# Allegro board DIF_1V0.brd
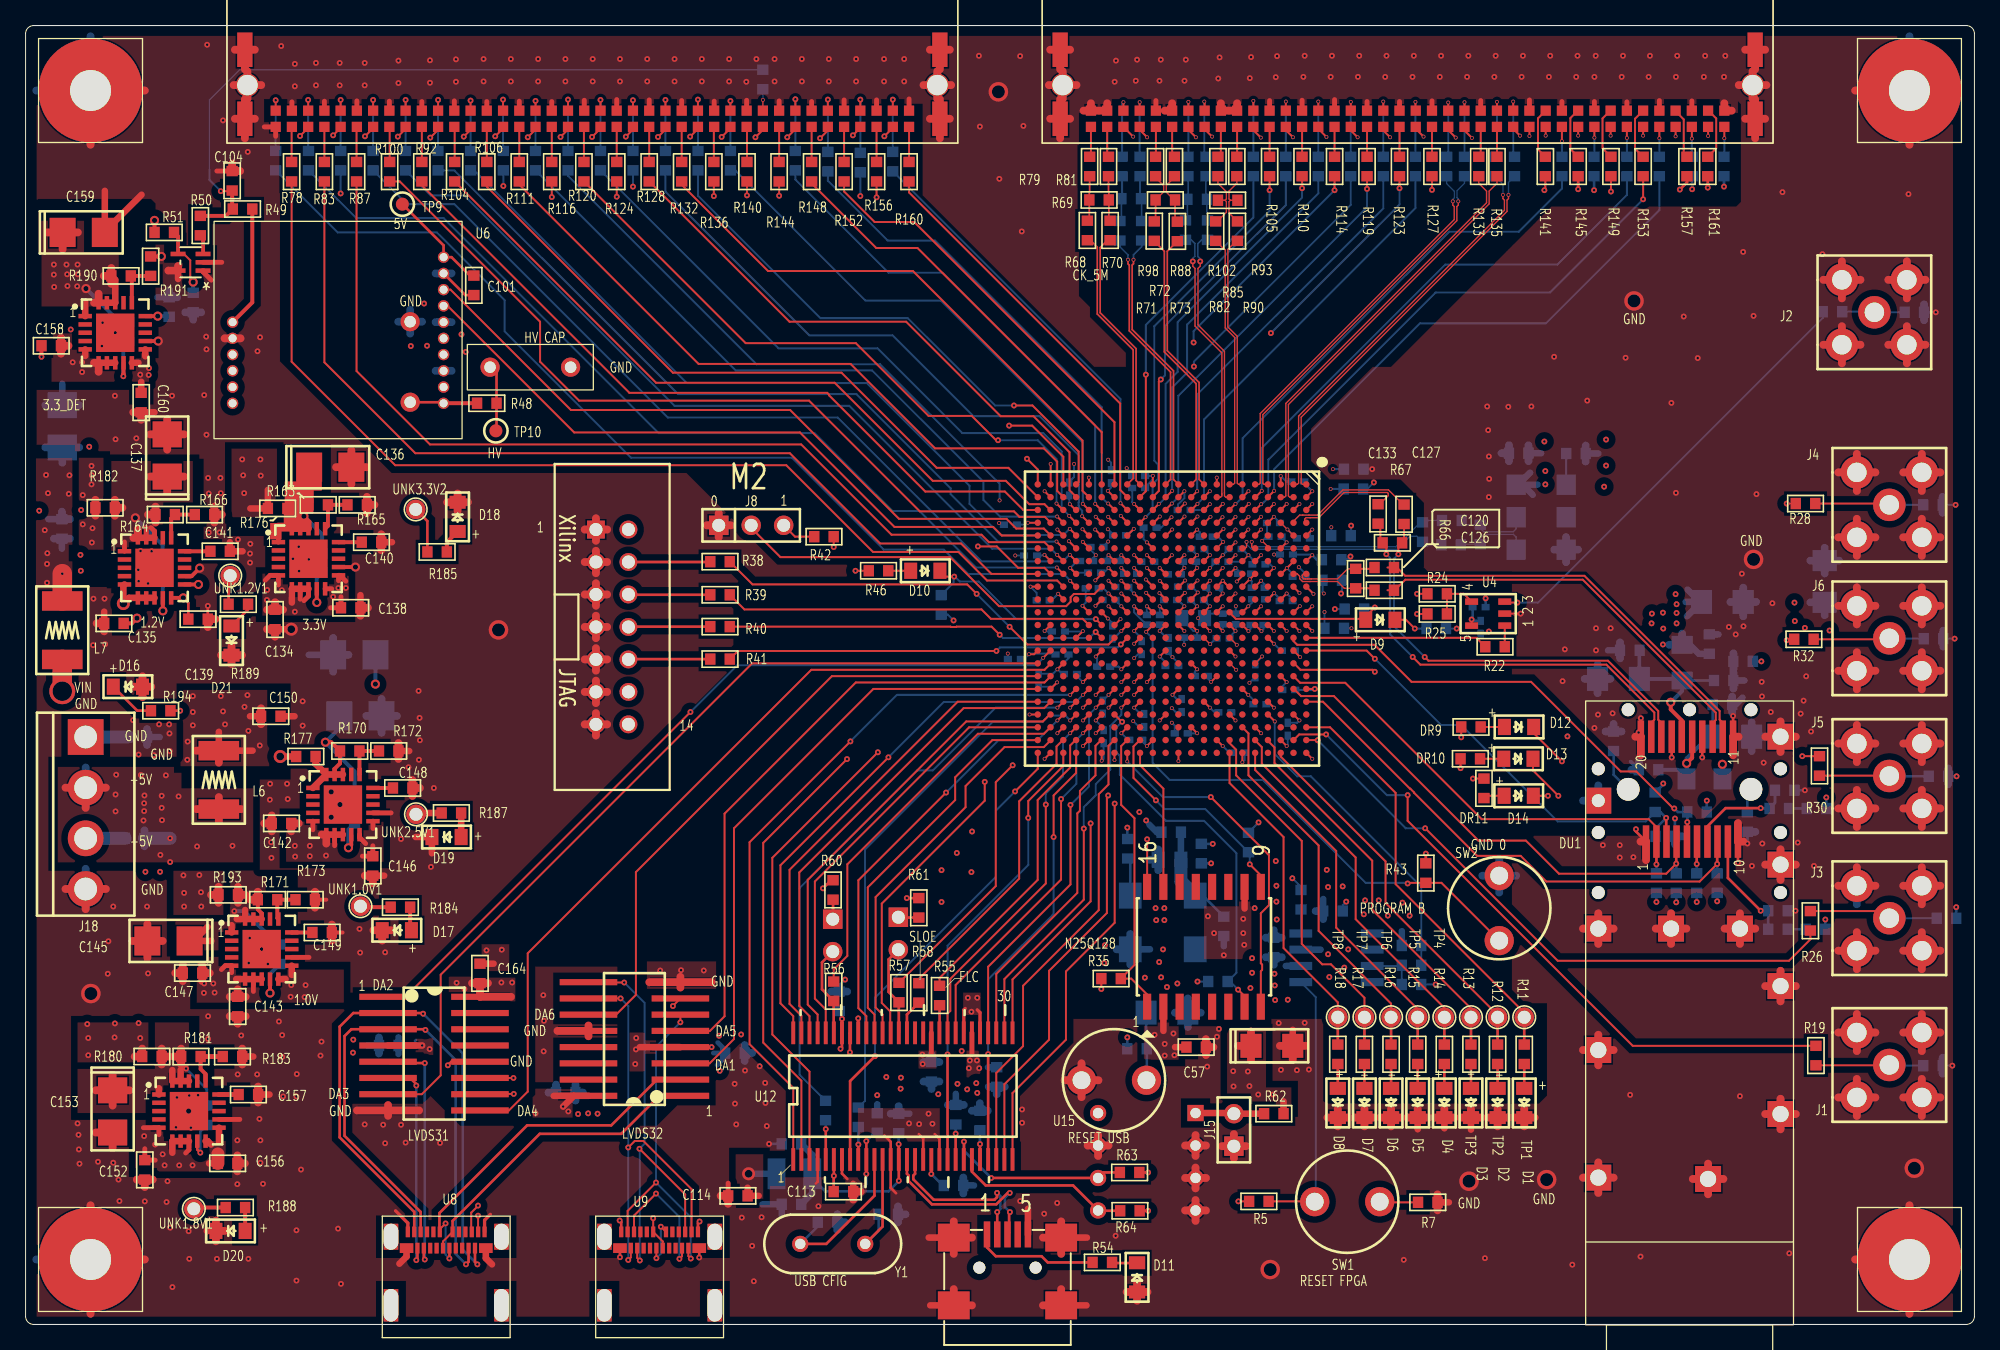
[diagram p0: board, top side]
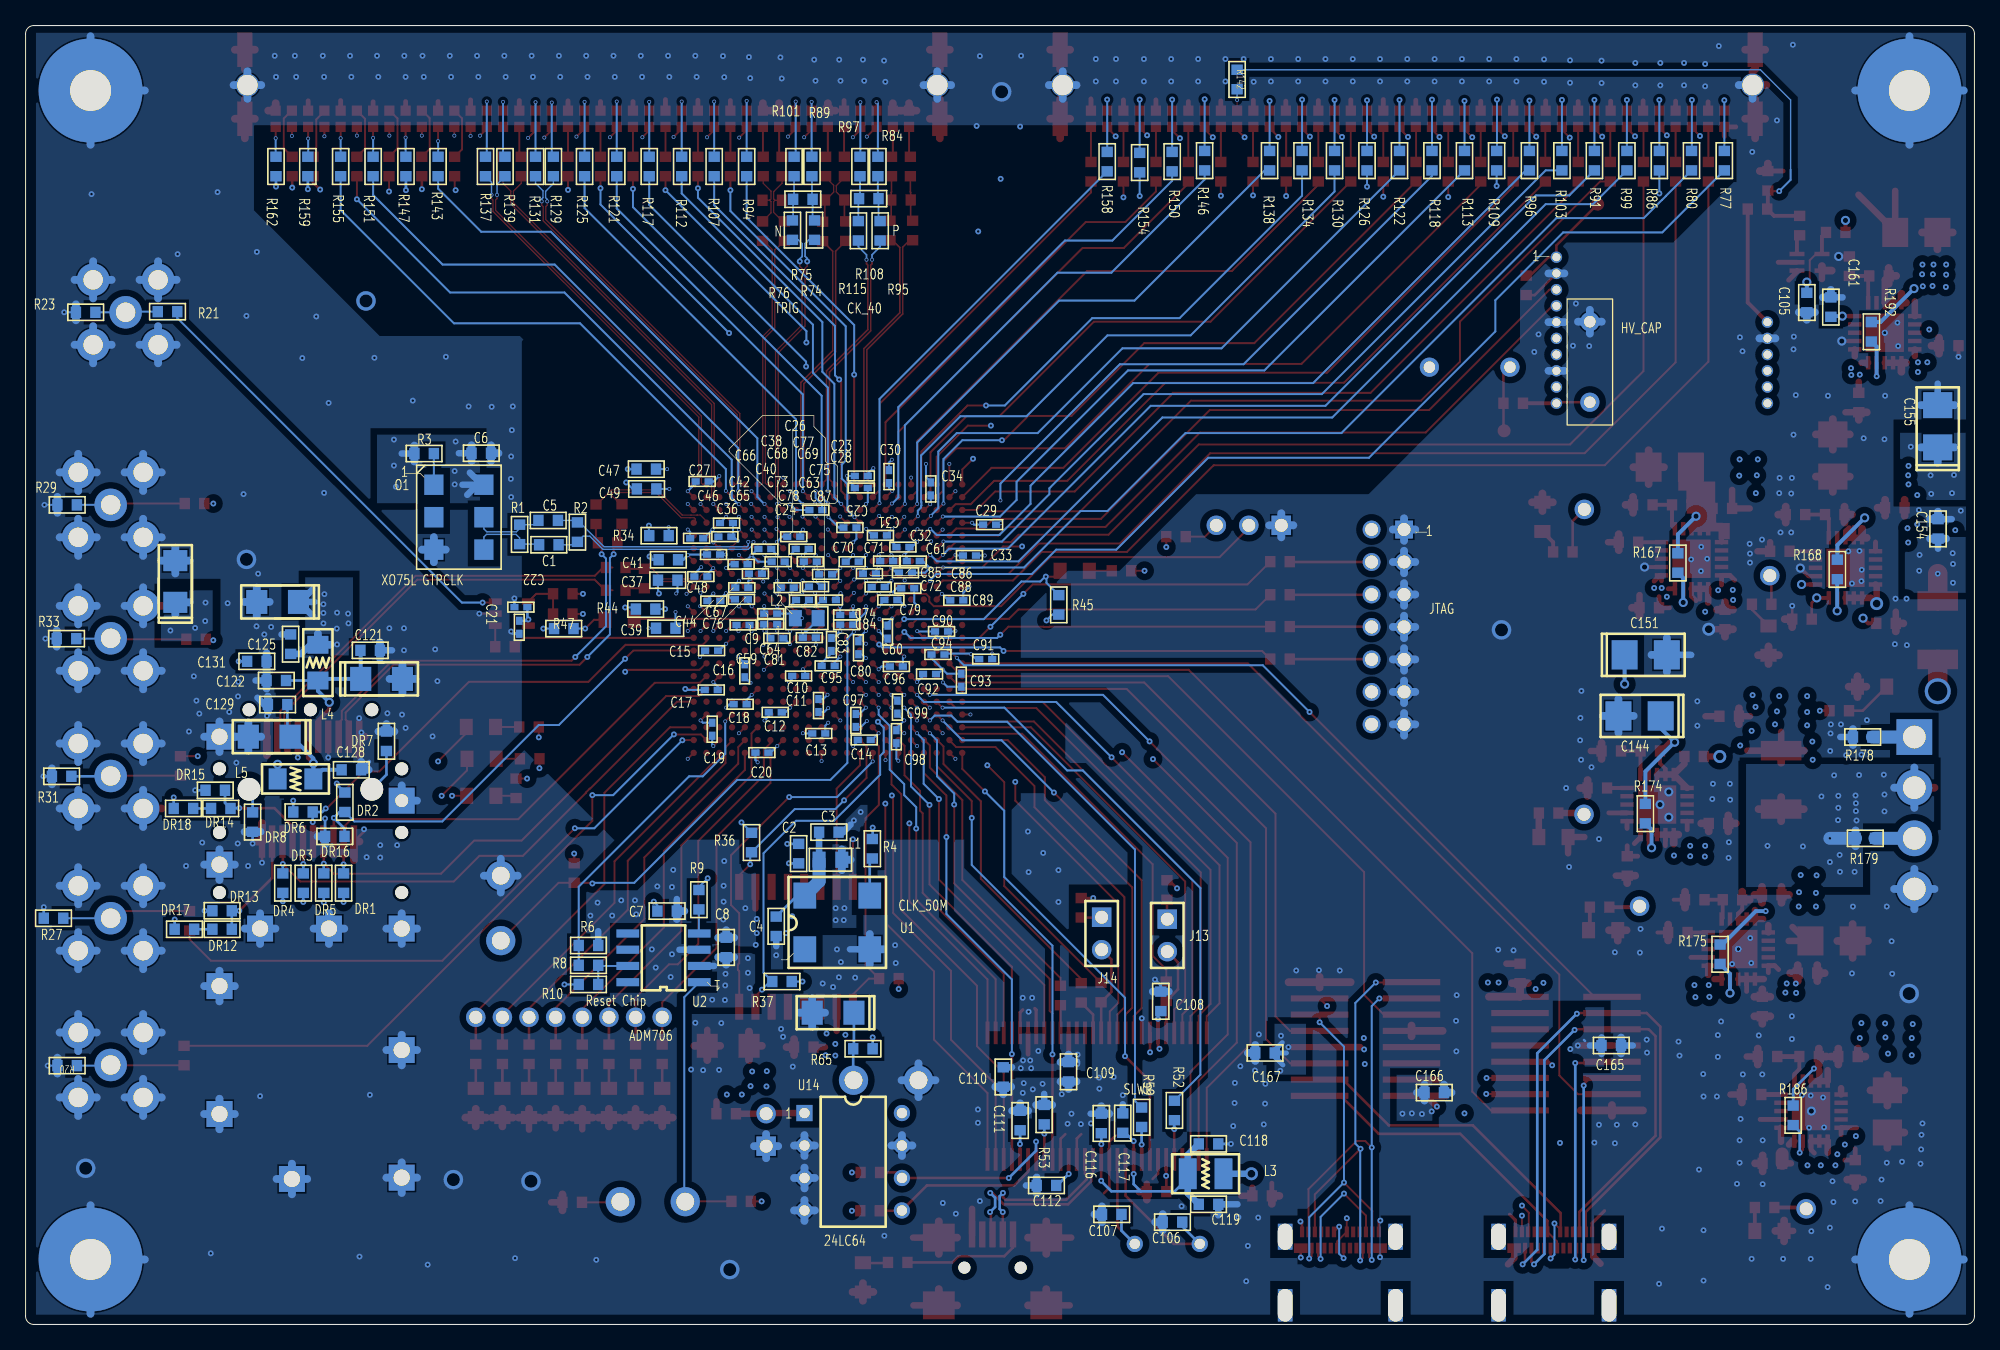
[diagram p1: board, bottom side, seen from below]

Outline 152.4 x 101.6 mm; copper layers: TOP, ART2, PLANE3, GND4, PLANE5, GND6, PLANE7, BOTTOM. Coordinates in mm from the lower left corner of the outline.
Outline path: 0,100.97 0,0.64 arc(0.19,0.19) 0.64,0 151.76,0 arc(152.21,0.19) 152.4,0.64 152.4,100.97 arc(152.21,101.41) 151.76,101.6 0.64,101.6 arc(0.19,101.41) 0,100.97

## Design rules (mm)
net group 5.0V_HV: nets N16783629 N16783633
net group CK_40M_F: nets N31992 N31996
net group CLK_5M_F: nets N31695 N31699
net group GTP1: nets N16065 N16069
net group GTP2: nets N16073 N16077
net group GTP_REFCLK: nets N63573 N65349
net group IN_MONITOR: nets IN_MONITOR N16789996
net group IO_PRE_2.5_1: nets IO_PRE_2.5_1 N16790016
net group IO_PRE_2.5_2: nets IO_PRE_2.5_2 N16840818
net group IO_PRE_2.5_3: nets IO_PRE_2.5_3 N16841427
net group IO_PRE_2.5_4: nets IO_PRE_2.5_4 N16790120
net group IO_PRE_2.5_5: nets IO_PRE_2.5_5 N16790006
net group IO_PRE_2.5_6: nets IO_PRE_2.5_6 N16841941
net group IO_PRE_2.5_7: nets IO_PRE_2.5_7 N16790130
net group IO_PRE_2.5_8: nets IO_PRE_2.5_8 N16790031
net group IO_PRE_2.5_9: nets IO_PRE_2.5_9 N16790140
net group IO_PRE_2.5_10: nets IO_PRE_2.5_10 N16790036
net group IO_PRE_2.5_11: nets IO_PRE_2.5_11 N16790145
net group IO_PRE_3.3_1: nets IO_PRE_3.3_1 N16783654
net group IO_PRE_3.3_2: nets IO_PRE_3.3_2 N1678375638
net group IO_PRE_3.3_3: nets IO_PRE_3.3_3 N16783650
net group IO_PRE_3.3_4: nets IO_PRE_3.3_4 N1678375636
net group IO_PRE_3.3_5: nets IO_PRE_3.3_5 N16783646
net group IO_PRE_3.3_6: nets IO_PRE_3.3_6 N1678375634
net group IO_PRE_3.3_7: nets IO_PRE_3.3_7 N16783642
net group IO_PRE_3.3_8: nets IO_PRE_3.3_8 N1678375632
net group IO_PRE_3.3_9: nets IO_PRE_3.3_9 N16783637
net group IO_PRE_3.3_10: nets IO_PRE_3.3_10 N1678375628
net group IO_PRE_3.3_11: nets IO_PRE_3.3_11 N16783603
net group IO_PRE_3.3_12: nets IO_PRE_3.3_12 N1678375618
net group IO_PRE_3.3_13: nets IO_PRE_3.3_13 N1678375624
net group IO_PRE_3.3_14: nets IO_PRE_3.3_14 N16783624
net group IO_PRE_3.3_15: nets IO_PRE_3.3_15 N1678375626
net group N65373: nets N65373 N607665
net group N606320: nets N65361 N606320
net group N16783572: nets N39711 N16783572
net group N16783577: nets N39253 N16783577
net group N16783581: nets N38992 N16783581
net group N16783585: nets N34554 N16783585
net group N16783590: nets N38404 N16783590
net group N16783594: nets N38396 N16783594
net group N16783598: nets N36779 N16783598
net group N16783607: nets N40733 N16783607
net group N16783611: nets N42476 N16783611
net group N16783616: nets N42251 N16783616
net group N16783620: nets N41303 N16783620
net group N16789976: nets N33890 N16789976
net group N16789981: nets N28287 N16789981
net group N16789986: nets N27930 N16789986
net group N16789991: nets N27061 N16789991
net group N16790001: nets N29237 N16790001
net group N16790021: nets N72632 N16790021
net group N16790026: nets N16790026 N16790135
net group N16790085: nets N33886 N16790085
net group N16790090: nets N27703 N16790090
net group N16790095: nets N26834 N16790095
net group N16790100: nets N73220 N16790100
net group N16790105: nets N29233 N16790105
net group N16790110: nets N71766 N16790110
net group N167837560: nets N39940 N167837560
net group N167837562: nets N39482 N167837562
net group N167837564: nets N73812 N167837564
net group N167837566: nets N38635 N167837566
net group N167837568: nets N34550 N167837568
net group N1678375610: nets N38400 N1678375610
net group N1678375612: nets N36552 N1678375612
net group N1678375614: nets N37008 N1678375614
net group N1678375616: nets N40729 N1678375616
net group N1678375620: nets N42480 N1678375620
net group N1678375622: nets N42028 N1678375622
net group N1678375630: nets N64910 N1678375630
net group OUT_CK_5N_1: nets N16790060 OUT_CK_5N_1
net group OUT_CK_5P_1: nets N1679025740 OUT_CK_5P_1
net group OUT_CK_40N_1: nets N16838243 OUT_CK_40N_1
net group OUT_CK_40P_1: nets N16789956 OUT_CK_40P_1
net group OUT_RAZ_CHN_N_1: nets N16790080 OUT_RAZ_CHN_N_1
net group OUT_RAZ_CHN_P_1: nets N16839910 OUT_RAZ_CHN_P_1
net group OUT_TRIG_EXT_N_1: nets N16839386 OUT_TRIG_EXT_N_1
net group OUT_TRIG_EXT_P_1: nets N16789966 OUT_TRIG_EXT_P_1
net group OUT_VAL_EVT_N_1: nets N16790070 OUT_VAL_EVT_N_1
net group OUT_VAL_EVT_P_1: nets N16838862 OUT_VAL_EVT_P_1
net group RAZ_CHN_F: nets N33117 N33121
net group REFCLK: nets REFCLK+ REFCLK-
net group SFP_RD: nets GTP0_RD+ GTP0_RD-
net group SFP_TD: nets GTP0_TD+ GTP0_TD-
net group TRIG_EXP_F: nets N32289 N32293
net group USB_DATA: nets N16778188 N16778190
net group VAL_EVT_F: nets N31078 N31082
net group 1.2V: nets N17024
net group 3.3V_OUT_DET: nets N16790041 N16790052 N16790150 N16790155

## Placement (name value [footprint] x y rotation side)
C1  0.1u  [SC0603]  111.48 60.99 180 bottom
C2  0.1u  [SC0603]  91.95 36.83 270 bottom
C3  0.01u  [SC0603]  89.59 38.51 0 bottom
C4  1000p  [SC0603]  93.7 31.14 90 bottom
C5  0.1u  [SC0603]  111.53 62.89 180 bottom
C6  0.01u  [SC0603]  116.76 68.15 180 bottom
C7  0.01u  [SC0603]  102.23 32.33 180 bottom
C8  1u  [SC0603]  97.61 29.49 90 bottom
C9  1uf  [SC0402]  93.65 53.67 0 bottom
C10  0.01uf  [SC0402]  91.95 50.72 180 bottom
C11  1uf  [SC0402]  90.4 48.41 270 bottom
C12  0.01uf  [SC0402]  93.78 47.88 180 bottom
C13  1uf  [SC0402]  90.37 46.23 180 bottom
C14  0.01uf  [SC0402]  86.82 45.72 180 bottom
C15  1uf  [SC0402]  98.76 52.7 180 bottom
C16  0.01uf  [SC0402]  96.16 51.13 270 bottom
C17  1uf  [SC0402]  98.78 49.63 180 bottom
C18  0.01uf  [SC0402]  96.52 48.51 180 bottom
C19  1uf  [SC0402]  98.7 46.56 90 bottom
C20  0.01uf  [SC0402]  94.82 44.73 180 bottom
C21  0.1uF  [SC0402]  113.79 54.53 270 bottom
C22  0.01uf  [SC0402]  113.67 56.11 0 bottom
C23  1uf  [SC0402]  87.05 66.37 180 bottom
C24  0.01uf  [SC0402]  90.6 63.7 180 bottom
C25  1uf  [SC0402]  87.93 62.33 180 bottom
C26  0.01uf  [SC0402]  92.33 61.62 180 bottom
C27  1uf  [SC0402]  99.49 65.94 0 bottom
C28  0.01uf  [SC0402]  87.05 65.43 180 bottom
C29  1uf  [SC0402]  77.01 62.56 180 bottom
C30  0.01uf  [SC0402]  84.89 66.32 90 bottom
C31  1uf  [SC0402]  85.55 61.72 180 bottom
C32  0.01uf  [SC0402]  83.79 60.81 0 bottom
C33  1uf  [SC0402]  78.59 60.15 180 bottom
C34  0.01uf  [SC0402]  81.61 65.35 90 bottom
C36  0.1uF  [SC0402]  98.6 60.22 0 bottom
C37  4.7uf  [SC0603]  102.18 58.22 0 bottom
C38  0.1uF  [SC0402]  94.59 60.66 180 bottom
C39  4.7uf  [SC0603]  102.34 54.46 0 bottom
C40  0.1uF  [SC0402]  95.33 58.72 180 bottom
C41  4.7uf  [SC0603]  102.13 59.82 180 bottom
C42  0.1uF  [SC0402]  97.59 62.69 0 bottom
C44  0.1uF  [SC0402]  98.58 56.59 0 bottom
C46  0.1uF  [SC0402]  99.92 61.49 0 bottom
C47  4.7uf  [SC0603]  103.86 66.9 0 bottom
C48  0.1uF  [SC0402]  99.59 58.5 0 bottom
C49  4.7uf  [SC0603]  103.84 65.35 0 bottom
C57  0.1uF  [SC0603]  91.54 21.69 0 top
C58  10uF  [CT1206]  97.46 21.79 0 top
C59  1uf  [SC0402]  96.29 54.71 0 bottom
C60  0.01uf  [SC0402]  84.99 54.15 270 bottom
C61  1uf  [SC0402]  82.98 59.72 180 bottom
C63  1uf  [SC0402]  90.63 57.71 180 bottom
C64  0.01uf  [SC0402]  94.13 55.6 0 bottom
C65  1uf  [SC0402]  97.71 61.62 0 bottom
C66  0.01uf  [SC0402]  96.44 59.46 0 bottom
C67  1uf  [SC0402]  96.39 57.63 0 bottom
C68  0.01uf  [SC0402]  93.55 59.66 180 bottom
C69  1uf  [SC0402]  91.03 59.66 180 bottom
C70  0.01uf  [SC0402]  87.76 59.66 180 bottom
C71  1uf  [SC0402]  85.06 59.72 180 bottom
C72  0.01uf  [SC0402]  85.72 57.68 180 bottom
C73  1uf  [SC0402]  92.84 57.63 180 bottom
C74  0.01uf  [SC0402]  88.19 55.5 0 bottom
C75  1uf  [SC0402]  89.84 58.67 0 bottom
C76  0.01uf  [SC0402]  96.42 56.72 180 bottom
C77  1uf  [SC0402]  91.67 60.66 180 bottom
C78  0.01uf  [SC0402]  91.64 56.67 180 bottom
C79  1uf  [SC0402]  84.73 56.67 180 bottom
C80  0.01uf  [SC0402]  87.27 52.93 270 bottom
C81  1uf  [SC0402]  94.13 54.76 0 bottom
C82  0.01uf  [SC0402]  91.11 53.72 180 bottom
C83  1uf  [SC0402]  89.38 53.19 270 bottom
C84  0.01uf  [SC0402]  88.19 54.74 180 bottom
C85  1uf  [SC0402]  86.41 58.72 180 bottom
C86  0.01uf  [SC0402]  83.59 58.8 180 bottom
C87  1uf  [SC0402]  89.53 56.67 180 bottom
C88  0.01uf  [SC0402]  83.41 57.58 180 bottom
C89  1uf  [SC0402]  79.58 56.64 180 bottom
C90  0.01uf  [SC0402]  80.77 54.2 180 bottom
C91  1uf  [SC0402]  77.32 52.04 180 bottom
C92  0.01uf  [SC0402]  81.71 50.88 180 bottom
C93  1uf  [SC0402]  79.22 50.39 90 bottom
C94  0.01uf  [SC0402]  81.05 52.4 0 bottom
C95  1uf  [SC0402]  89.64 51.51 0 bottom
C96  0.01uf  [SC0402]  84.3 51.46 180 bottom
C97  1uf  [SC0402]  87.48 47.24 270 bottom
C98  0.01uf  [SC0402]  84.3 45.97 270 bottom
C99  1uf  [SC0402]  84.23 48.29 90 bottom
C101  0.1u  [SC0603]  35.05 81.28 90 top
C102  47n  [CHV]  30.07 72.14 90 bottom
C103  47n  [CHV]  36.32 74.88 0 top
C104  0.1u  [SC0603]  16.15 89.46 90 top
C105  0.1u  [SC0603]  13.11 79.93 270 bottom
C106  12pF  [SC0603]  62.71 8 180 bottom
C107  12pF  [SC0603]  67.46 8.61 180 bottom
C108  0.1uF  [SC0603]  63.63 25.27 270 bottom
C109  0.1uF  [SC0603]  70.84 19.76 90 bottom
C110  0.1uF  [SC0603]  75.95 19.35 90 bottom
C111  0.1uF  [SC0603]  74.63 15.95 270 bottom
C112  0.1uF  [SC0603]  72.57 10.87 180 bottom
C113  0.1uF  [SC0603]  63.96 10.39 180 top
C114  0.1uF  [SC0603]  55.7 10.06 0 top
C115  10uF  [CT1206]  89.26 24.38 0 bottom
C116  0.1uF  [SC0603]  68.28 15.72 270 bottom
C117  0.1uF  [SC0603]  66.6 15.75 270 bottom
C118  10uF  [SC0603]  59.89 14.12 0 bottom
C119  0.1uF  [SC0603]  59.89 9.4 0 bottom
C120  0.1uF  [SC0603]  106.25 59.21 180 top
C121  1uF  [SC0603]  125.45 52.73 180 bottom
C122  0.1uF  [SC0603]  132.79 50.37 0 bottom
C123  10uF  [CT1206]  124.56 50.5 180 bottom
C124  10uF  [CT1206]  140.69 58.12 90 bottom
C125  0.1uF  [SC0603]  131.67 53.21 90 bottom
C126  0.1uF  [SC0603]  106.25 57.43 180 top
C127  0.1uF  [SC0603]  107.8 63.37 270 top
C128  1uF  [SC0603]  126.92 43.38 180 bottom
C129  0.1uF  [SC0603]  132.69 48.49 0 bottom
C130  10uF  [CT1206]  133.35 45.97 0 bottom
C131  0.1uF  [SC0603]  134.32 51.87 180 bottom
C132  10uF  [CT1206]  132.69 56.52 0 bottom
C133  0.1uF  [SC0603]  105.77 63.4 270 top
C134  1u  [SC0603]  19.51 55.14 270 top
C135  1u  [SC0603]  6.91 54.84 180 top
C136  10u  [STC3528]  23.83 67.06 0 top
C137  10u  [STC3528]  11.07 67.97 90 top
C138  1u  [SC0603]  25.43 56.06 0 top
C139  1u  [SC0603]  13.49 55.17 0 top
C140  470p  [SC0603]  27.05 61.19 0 top
C141  470p  [SC0603]  15.21 60.48 0 top
C142  1u  [SC0603]  20.02 39.19 180 top
C143  1u  [SC0603]  16.59 24.87 270 top
C144  10u  [STC3528]  26.19 47.6 0 bottom
C145  10u  [STC3528]  11.18 30 180 top
C146  1u  [SC0603]  27.15 35.86 270 top
C147  1u  [SC0603]  13.06 27.48 180 top
C148  470p  [SC0603]  29.49 41.96 0 top
C149  470p  [SC0603]  23.19 30.66 0 top
C150  0.1u  [SC0603]  19.18 47.57 0 top
C151  10u  [STC3528]  25.7 52.37 180 bottom
C152  1u  [SC0603]  9.32 12.09 270 top
C153  10u  [STC3528]  6.81 16.66 270 top
C154  0.1u  [SC0603]  2.84 62.23 90 bottom
C155  10u  [STC3528]  2.87 70.26 90 bottom
C156  1u  [SC0603]  15.8 12.6 0 top
C157  470p  [SC0603]  17.42 17.98 0 top
C158  1u  [SC0603]  2.01 76.56 180 top
C159  10u  [STC3528]  4.55 85.42 0 top
C160  1u  [SC0603]  9.04 72.11 270 top
C161  470p  [SC0603]  11.23 79.58 90 bottom
C164  0.1uF  [SC0603]  35.53 27.46 270 top
C165  0.1uF  [SC0603]  28.4 21.82 0 bottom
C166  0.1uF  [SC0603]  42.24 18.14 0 bottom
C167  0.1uF  [SC0603]  55.47 21.23 180 bottom
D1  LED  [SD0805]  117.2 17.32 90 top
D2  LED  [SD0805]  115.11 17.32 90 top
D3  LED  [SD0805]  113.03 17.32 90 top
D4  LED  [SD0805]  110.95 17.32 90 top
D5  LED  [SD0805]  108.86 17.32 90 top
D6  LED  [SD0805]  106.78 17.32 90 top
D7  LED  [SD0805]  104.7 17.32 90 top
D8  LED  [SD0805]  102.62 17.32 90 top
D9  LED  [SD0805]  105.94 55.12 180 top
D10  LED  [SD0805]  70.36 58.95 180 top
D11  LED  [SD0805]  86.92 3.68 270 top
D12  LED  [SD0805]  116.79 46.74 180 top
D13  LED  [SD0805]  116.74 44.25 180 top
D14  LED  [SD0805]  116.76 41.35 180 top
D16  Green  [SD0805]  8 49.89 0 top
D17  LED  [SD0805]  29.03 30.84 0 top
D18  LED  [SD0805]  33.78 63.17 270 top
D19  LED  [SD0805]  32.92 38.13 0 top
D20  LED  [SD0805]  16.03 7.32 0 top
D21  LED  [SD0805]  16.1 53.49 90 top
DR1  4.7K  [SR0603]  127.53 34.52 270 bottom
DR2  4.7K  [SR0603]  127.43 40.84 90 bottom
DR3  4.7K  [SR0603]  130.68 34.52 270 bottom
DR4  4.7K  [SR0603]  132.28 34.52 270 bottom
DR5  4.7K  [SR0603]  129.08 34.52 270 bottom
DR6  4.7K  [SR0603]  130.71 40.08 0 bottom
DR7  null  [SR0603]  124.18 45.62 90 bottom
DR8  null  [SR0603]  134.65 39.29 270 bottom
DR9  4.7K  [SR0603]  113.03 46.74 180 top
DR10  4.7K  [SR0603]  112.98 44.25 180 top
DR11  4.7K  [SR0603]  114.05 41.94 90 top
DR12  4.7K  [SR0603]  137.03 30.91 0 bottom
DR13  4.7K  [SR0603]  137.03 32.36 0 bottom
DR14  4.7K  [SR0603]  137.13 40.36 0 bottom
DR15  4.7K  [SR0603]  137.57 41.78 0 bottom
DR16  4.7K  [SR0603]  128.22 38.18 0 bottom
DR17  4.7K  [SR0603]  139.98 30.91 180 bottom
DR18  4.7K  [SR0603]  140.06 40.36 180 bottom
DU1  74441-0010  [LASER22-4816-M]  126.72 37.77 90 top
J1  SMA  [CON-BNC-S-T]  145.75 20.29 0 top
J2  SMA  [CON-BNC-S-T]  144.58 79.17 0 top
J3  SMA  [CON-BNC-S-T]  145.75 31.78 0 top
J4  SMA  [CON-BNC-S-T]  145.75 64.11 0 top
J5  SMA  [CON-BNC-S-T]  145.75 42.9 0 top
J6  SMA  [CON-BNC-S-T]  145.75 53.67 0 top
J7  JTAG  [JTAG-14P]  41.38 67.31 270 top
J8  MSEL0  [SIP-3P]  56.74 62.51 0 top
J9  2mm_Hole  [2MM_HOLE]  147.32 96.52 0 top
J10  2mm_Hole  [2MM_HOLE]  147.32 5.08 0 top
J11  2mm_Hole  [2MM_HOLE]  5.08 96.52 0 top
J12  2mm_Hole  [2MM_HOLE]  5.08 5.08 0 top
J13  WU =1  [SIP-2P]  63.12 30.43 270 bottom
J14  WU2 =1  [SIP-2P]  68.25 30.58 270 bottom
J15  addrCS  [SIP-2P]  94.49 15.21 90 top
J16  CONN  [154744-ERNI]  19.56 94.95 90 top
J17  CONN  [154744-ERNI]  83.31 94.95 90 top
J18  Power In  [SIP-4P-156]  4.7 40.01 270 top
L1  BEAD  [SL0805]  89.46 36.35 0 bottom
L2  BEAD  [SL0805]  91.31 55.24 180 bottom
L3  Bead  [SL1210]  60.12 11.79 0 bottom
L4  39mH  [SL1206]  129.54 51.77 90 bottom
L5  39mH  [SL1206]  131.29 42.67 0 bottom
L6  10uH  [SL1812]  15.11 42.6 90 top
L7  10uH  [SL1812]  2.87 54.31 90 top
NOREF  -  []  114.33 87.96 0 top
NOREF#2  -  []  115.67 88.06 0 top
NOREF#3  -  []  0.64 101.6 0 top
NOREF#4  -  []  119.02 51.82 0 top
NOREF#5  -  []  83.85 81.08 0 top
NOREF#6  -  []  30.78 11.07 0 top
NOREF#7  -  []  91.54 81.51 0 top
NOREF#8  -  []  33.93 11.63 0 top
NOREF#9  -  []  5.08 96.52 0 top
NOREF#10  -  []  45.24 12.57 0 top
NOREF#11  -  []  89.26 82.5 0 top
NOREF#12  -  []  47.6 13.67 0 top
NOREF#13  -  []  117.42 58.39 0 top
NOREF#14  -  []  35.03 8.66 0 top
NOREF#15  -  []  49.63 10.72 0 top
NOREF#16  -  []  30.89 13.23 0 top
NOREF#17  -  []  32.69 22.1 0 top
NOREF#18  -  []  93.83 82.73 0 top
NOREF#19  -  []  0 0.64 90 top
NOREF#20  -  []  86.23 81.56 0 top
NOREF#21  -  []  5.08 5.08 90 top
NOREF#22  -  []  74.09 9.55 0 top
NOREF#23  -  []  24.87 21.59 0 top
NOREF#24  -  []  111.86 86.92 0 top
O1  100M  [XO75L]  118.52 63.14 270 bottom
R1  null  [SR0603]  113.77 61.8 90 bottom
R2  100  [SR0603]  109.25 61.98 90 bottom
R3  4.7K  [SR0603]  121.23 68.12 0 bottom
R4  33  [SR0603]  86.18 37.21 90 bottom
R5  10k  [SR0603]  96.44 9.63 180 top
R6  330  [SR0603]  108.38 29.64 0 bottom
R7  1k  [SR0603]  109.65 9.55 0 top
R8  100  [SR0603]  108.38 28.09 180 bottom
R9  100k  [SR0603]  99.75 33.22 90 bottom
R10  100k  [SR0603]  108.38 26.59 180 bottom
R11  1k  [SR0603]  117.2 21.13 270 top
R12  1k  [SR0603]  115.11 21.13 270 top
R13  1k  [SR0603]  113.03 21.13 270 top
R14  1k  [SR0603]  110.95 21.13 270 top
R15  1k  [SR0603]  108.86 21.13 270 top
R16  1k  [SR0603]  106.78 21.13 270 top
R17  1k  [SR0603]  104.7 21.13 270 top
R18  1k  [SR0603]  102.62 21.13 270 top
R19  test  [SR0603]  140 21.03 90 top
R20  test  [SR0603]  149.15 20.24 0 bottom
R21  0  [SR0603]  141.3 79.22 180 bottom
R22  33  [SR0603]  114.91 53.01 180 top
R23  50  [SR0603]  147.7 79.17 0 bottom
R24  3k  [SR0603]  110.39 57.15 180 top
R25  4k  [SR0603]  110.39 55.58 180 top
R26  test  [SR0603]  139.57 31.57 270 top
R27  test  [SR0603]  150.22 31.78 0 bottom
R28  test  [SR0603]  139.19 64.21 180 top
R29  test  [SR0603]  149.15 64.11 0 bottom
R30  test  [SR0603]  140.28 43.69 90 top
R31  test  [SR0603]  149.58 42.88 0 bottom
R32  test  [SR0603]  139.06 53.59 180 top
R33  test  [SR0603]  149.2 53.64 0 bottom
R34  100  [SR0603]  102.87 61.7 0 bottom
R35  4.7K  [SR0603]  84.89 27.05 180 top
R36  4.7K  [SR0603]  95.63 37.69 90 bottom
R37  4.7K  [SR0603]  93.24 26.82 180 bottom
R38  33  [SR0603]  54.31 59.66 0 top
R39  33  [SR0603]  54.31 57.07 0 top
R40  33  [SR0603]  54.31 54.58 0 top
R41  33  [SR0603]  54.31 52.04 0 top
R42  4.7K  [SR0603]  62.43 61.62 180 top
R43  4.7K  [SR0603]  109.5 35.31 90 top
R44  300  [SR0603]  103.91 55.96 180 bottom
R45  4.7K  [SR0603]  71.6 56.29 270 bottom
R46  300  [SR0603]  66.7 58.95 180 top
R47  220  [SR0603]  110.31 54.43 180 bottom
R48  10  [SR0603]  36.07 72.06 0 top
R49  1k  [SR0603]  16.97 87.25 0 top
R50  1.5k  [SR0603]  13.67 85.95 270 top
R51  10  [SR0603]  10.85 85.42 0 top
R52  0  [SR0603]  62.56 16.74 270 bottom
R53  10k  [SR0603]  72.75 16.41 270 bottom
R54  4.7k  [SR0603]  84.2 4.85 180 top
R55  0  [SR0603]  71.48 25.73 90 top
R56  0 or null  [SR0603]  63.2 26.06 270 top
R57  0 or null  [SR0603]  68.3 25.96 270 top
R58  0  [SR0603]  69.85 25.93 90 top
R59  0  [SR0603]  65.13 16.21 90 bottom
R60  0  [SR0603]  63.14 33.99 90 top
R61  0  [SR0603]  69.85 32.59 90 top
R62  10k  [SR0603]  97.61 16.48 0 top
R63  2.2k  [SR0603]  86.33 11.89 0 top
R64  2.2k  [SR0603]  86.36 8.89 0 top
R65  20k  [SR0603]  86.92 21.56 180 bottom
R66  100  [SR0603]  104.01 58.34 90 top
R67  100  [SR0603]  106.88 61.14 0 top
R68  0  [SR0603]  83.03 85.57 90 top
R69  100  [SR0603]  83.95 87.96 180 top
R70  0  [SR0603]  84.81 85.57 270 top
R71  0  [SR0603]  88.27 85.52 90 top
R72  100  [SR0603]  89.13 87.96 180 top
R73  0  [SR0603]  90.07 85.5 270 top
R74  0  [SR0603]  90.7 85.6 90 bottom
R75  100  [SR0603]  91.62 88.01 180 bottom
R76  0  [SR0603]  92.43 85.6 270 bottom
R77  0  [SR0603]  19.56 91.03 90 bottom
R78  0  [SR0603]  20.8 90.17 270 top
R79  0  [SR0603]  83.21 90.58 270 top
R80  0  [SR0603]  22.12 91.03 90 bottom
R81  0  [SR0603]  84.68 90.58 270 top
R82  0  [SR0603]  93.07 85.52 90 top
R83  0  [SR0603]  23.37 90.17 270 top
R84  0  [SR0603]  85.75 90.58 90 bottom
R85  100  [SR0603]  94.01 87.93 180 top
R86  0  [SR0603]  24.64 91.03 90 bottom
R87  0  [SR0603]  25.88 90.17 270 top
R88  0  [SR0603]  89.84 90.58 270 top
R89  0  [SR0603]  90.91 90.58 90 bottom
R90  0  [SR0603]  94.77 85.52 270 top
R91  0  [SR0603]  29.72 91.03 90 bottom
R92  0  [SR0603]  30.99 90.17 270 top
R93  0  [SR0603]  94.72 90.58 270 top
R94  0  [SR0603]  96.01 90.58 90 bottom
R95  0  [SR0603]  85.57 85.55 90 bottom
R96  0  [SR0603]  34.8 91.03 90 bottom
R97  0  [SR0603]  87.15 90.58 90 bottom
R98  0  [SR0603]  88.37 90.58 270 top
R99  0  [SR0603]  27.18 91.03 90 bottom
R100  0  [SR0603]  28.47 90.17 270 top
R101  0  [SR0603]  92.3 90.58 90 bottom
R102  0  [SR0603]  93.24 90.58 270 top
R103  0  [SR0603]  32.26 91.03 90 bottom
R104  0  [SR0603]  33.55 90.17 270 top
R105  0  [SR0603]  97.28 90.58 270 top
R106  0  [SR0603]  36.07 90.17 270 top
R107  0  [SR0603]  98.55 90.58 90 bottom
R108  100  [SR0603]  86.46 88.06 180 bottom
R109  0  [SR0603]  37.36 91.03 90 bottom
R110  0  [SR0603]  99.82 90.58 270 top
R111  0  [SR0603]  38.61 90.17 270 top
R112  0  [SR0603]  101.09 90.58 90 bottom
R113  0  [SR0603]  39.88 91.03 90 bottom
R114  0  [SR0603]  102.36 90.58 270 top
R115  0  [SR0603]  87.27 85.55 270 bottom
R116  0  [SR0603]  41.15 90.17 270 top
R117  0  [SR0603]  103.63 90.58 90 bottom
R118  0  [SR0603]  42.42 91.03 90 bottom
R119  0  [SR0603]  104.9 90.58 270 top
R120  0  [SR0603]  43.66 90.17 270 top
R121  0  [SR0603]  106.17 90.58 90 bottom
R122  0  [SR0603]  44.96 91.03 90 bottom
R123  0  [SR0603]  107.44 90.58 270 top
R124  0  [SR0603]  46.23 90.17 270 top
R125  0  [SR0603]  108.69 90.58 90 bottom
R126  0  [SR0603]  47.5 91.03 90 bottom
R127  0  [SR0603]  109.98 90.58 270 top
R128  0  [SR0603]  48.77 90.17 270 top
R129  0  [SR0603]  111.12 90.58 90 bottom
R130  0  [SR0603]  50.04 91.03 90 bottom
R131  0  [SR0603]  112.52 90.58 90 bottom
R132  0  [SR0603]  51.31 90.17 270 top
R133  0  [SR0603]  113.64 90.58 270 top
R134  0  [SR0603]  52.58 91.03 90 bottom
R135  0  [SR0603]  115.06 90.58 270 top
R136  0  [SR0603]  53.82 90.17 270 top
R137  0  [SR0603]  116.43 90.58 90 bottom
R138  0  [SR0603]  55.12 91.03 90 bottom
R139  0  [SR0603]  114.91 90.58 90 bottom
R140  0  [SR0603]  56.41 90.17 270 top
R141  0  [SR0603]  118.85 90.58 90 top
R142  0  [SR0603]  57.66 97.38 270 bottom
R143  0  [SR0603]  120.14 90.58 270 bottom
R144  0  [SR0603]  58.93 90.17 270 top
R145  0  [SR0603]  121.41 90.58 90 top
R146  0  [SR0603]  60.2 91.03 90 bottom
R147  0  [SR0603]  122.66 90.58 270 bottom
R148  0  [SR0603]  61.47 90.17 270 top
R149  0  [SR0603]  123.98 90.58 90 top
R150  0  [SR0603]  62.74 90.96 90 bottom
R151  0  [SR0603]  125.22 90.58 270 bottom
R152  0  [SR0603]  64.01 90.17 270 top
R153  0  [SR0603]  126.49 90.58 90 top
R154  0  [SR0603]  65.28 90.88 90 bottom
R155  0  [SR0603]  127.76 90.58 270 bottom
R156  0  [SR0603]  66.55 90.17 270 top
R157  0  [SR0603]  129.92 90.58 90 top
R158  0  [SR0603]  67.82 90.96 90 bottom
R159  0  [SR0603]  130.33 90.58 270 bottom
R160  0  [SR0603]  69.09 90.17 270 top
R161  0  [SR0603]  131.55 90.58 90 top
R162  0  [SR0603]  132.82 90.58 270 bottom
R163  3.57k  [SR0603]  22.89 64.11 0 top
R164  2.49k  [SR0603]  10.92 63.35 0 top
R165  1.15k  [SR0603]  25.93 64.11 0 top
R166  4.99k  [SR0603]  14 63.35 0 top
R167  100k  [SR0603]  23.19 59.56 90 bottom
R168  100k  [SR0603]  10.72 59.05 90 bottom
R170  3.57k  [SR0603]  25.35 44.86 0 top
R171  1.13k  [SR0603]  18.92 33.22 0 top
R172  1.69k  [SR0603]  28.4 44.86 0 top
R173  4.53k  [SR0603]  21.87 33.22 0 top
R174  100k  [SR0603]  25.73 39.95 90 bottom
R175  100k  [SR0603]  19.89 28.96 90 bottom
R176  0  [SR0603]  19.71 63.83 180 top
R177  0  [SR0603]  21.92 44.42 180 top
R178  0  [SR0603]  8.74 45.95 0 bottom
R179  0  [SR0603]  8.53 38.02 0 bottom
R180  0  [SR0603]  9.88 20.95 180 top
R181  3.57k  [SR0603]  12.93 20.95 0 top
R182  0  [SR0603]  6.22 63.88 180 top
R183  2.87k  [SR0603]  16.18 20.95 0 top
R184  1.5k  [SR0603]  29.31 32.64 0 top
R185  1.5k  [SR0603]  32.18 60.43 0 top
R186  100k  [SR0603]  14.17 16.36 90 bottom
R187  1.5k  [SR0603]  33.3 40.01 0 top
R188  1.5k  [SR0603]  16.41 9.14 0 top
R189  1.5k  [SR0603]  16.64 56.34 0 top
R190  3.57k  [SR0603]  7.47 82.02 0 top
R191  1.15k  [SR0603]  9.78 82.78 90 top
R192  100k  [SR0603]  8.05 77.65 90 bottom
R193  0  [SR0603]  15.85 33.6 180 top
R194  1.5k  [SR0603]  10.57 48.01 180 top
SW1  pushbotton  [INDC2-200-M]  103.35 9.6 180 top
SW2  Button  [INDC2-200-M]  115.24 32.56 270 top
TP1  Signal  [GND40]  117.2 24.03 0 top
TP2  Signal  [GND40]  115.11 24.03 0 top
TP3  Signal  [GND40]  113.03 24.03 0 top
TP4  Signal  [GND40]  110.95 24.03 0 top
TP5  Signal  [GND40]  108.86 24.03 0 top
TP6  Signal  [GND40]  106.78 24.03 0 top
TP7  Signal  [GND40]  104.7 24.03 0 top
TP8  Signal  [GND40]  102.62 24.03 0 top
TP9  TEST POINT  [TP-40-SMD]  29.46 87.63 0 top
TP10  TEST POINT  [TP-40-SMD]  36.78 69.9 0 top
U1  osc  [SX4-0705]  88.93 31.45 180 bottom
U2  ADM706RAR  [SOP8-50-160]  102.51 28.68 90 bottom
U3  XC7A100T  [ARTIX7XCA100T484]  100.15 65.71 270 top
U4  ADCMP600  [SOT23-5]  114.38 55.6 90 top
U5  N25Q128  [SO16_50P300X413]  92.15 29.54 90 top
U6  C11204-01  [C11204_01]  34.14 86.28 180 top
U7  LM94021  [MAA05A]  12.9 83.08 180 top
U8  USBTypeCPlug  [USB_TYPEC_PLUG_V1]  32.89 5.97 0 top
U9  USBTypeCPlug  [USB_TYPEC_PLUG_V1]  49.58 5.97 0 top
U10  SN65LVDS31D  [CFP16ANDSOIC16]  28.57 16.03 0 top
U11  SN65LVDS32D  [CFP16ANDSOIC16]  50.98 27.48 180 top
U12  CY7C68013  [SOP56-25-300]  68.61 17.86 0 top
U13  USBCON  [CONN_USB_B_CHL]  76.78 3 0 top
U14  24LC64  [DIP8-100-300]  87.68 12.73 270 bottom
U15  PushButton  [INDC2-200-M]  85.12 19.1 0 top
U16  TPS74401  [QFN65P500X500-21]  22.12 59.89 0 top
U17  TPS74401  [QFN65P500X500-21]  10.08 59.18 0 top
U18  TPS74401  [QFN65P500X500-21]  18.47 29.36 0 top
U19  TPS74401  [QFN65P500X500-21]  24.82 40.67 0 top
U20  TPS74401  [QFN65P500X500-21]  12.78 16.69 0 top
U21  TPS74401  [QFN65P500X500-21]  7.01 77.57 0 top
UNK1.0V1  3.3V  [GND40]  26.19 32.72 0 top
UNK1.2V1  3.3V  [GND40]  16 58.57 0 top
UNK1.8V1  1.2V  [GND40]  13.16 9.04 0 top
UNK2.5V1  3.3V  [GND40]  30.53 39.9 0 top
UNK3.3V2  3.3V  [GND40]  30.51 63.75 0 top
Y1  24MHz  [XTAL2-200A]  63.12 6.3 180 top

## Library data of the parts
C1 C5 C6 = C NP
C2 = C: signal model: DEFAULT_CAPACITOR_1e-07pF_1_2
C3 = C: signal model: DEFAULT_CAPACITOR_1e-08pF_1_2
C4 = C: signal model: DEFAULT_CAPACITOR_1e-09pF_1_2
C7 = CAP NP: signal model: DEFAULT_CAPACITOR_1e-08pF_1_2
C8 = CAP NP: signal model: DEFAULT_CAPACITOR_1e-06pF_1_2
C9 C11 C13 C15 C17 C19 C23 C25 C27 C29 C31 C33 C65 C67 C69 C71 C73 C75 C77 C79 C81 C83 C85 C87 C89 C91 C93 C95 C97 C99 = CAP NP: signal model: DEFAULT_CAPACITOR_1e+06pF_1_2
C10 C12 C14 C16 C18 C20 C24 C26 C28 C30 C32 C34 C66 C68 C70 C72 C74 C76 C78 C80 C82 C84 C86 C88 C90 C92 C94 C96 C98 = CAP NP: signal model: DEFAULT_CAPACITOR_10000pF_1_2
C21 C22 C57 C59-C61 C63 C64 C101-C114 C116-C122 C125-C129 C131 C133 C164-C167 = CAP NP
C36 C38 C40 C42 C44 C46 C48 = CAP NP: signal model: DEFAULT_CAPACITOR_100000pF_1_2
C37 C39 C41 C47 C49 = CAP NP: signal model: DEFAULT_CAPACITOR_4.7e+06pF_1_2
C58 C123 C124 C130 C132 = C
C115 = CAP POL
C134 C135 C138-C143 C146-C150 C152 C154 C156-C158 C160 C161 = Capacitor np
C136 C137 C144 C145 C151 C153 C155 C159 = Capacitor pol
D1-D14 D16-D21 = LED
DR1-DR18 R1-R3 R11-R33 R35-R76 R82 R85 R90 R95 R108 R115 R184 R185 R187-R189 = R
DU1 = 74441-0010
J1-J6 = SMA_0
J7 = JTAG
J8 = CON3
J9-J12 = 2mm_Hole
J13-J15 = CON2
J16 J17 = CONN_1
J18 = 4 HEADER
L1 = INDUCTOR: signal model: DEFAULT_INDUCTOR_0.001nH_1_2
L2-L5 = INDUCTOR
L6 L7 = Inductor
O1 = OSC_DIFF
R4 = R: signal model: DEFAULT_RESISTOR_33.000000OHM_1_2
R5 = R: signal model: DEFAULT_RESISTOR_10000OHM_1_2
R6 = R: signal model: DEFAULT_RESISTOR_330.000000OHM_1_2
R7 = R: signal model: DEFAULT_RESISTOR_1000.000000OHM_1_2
R8 R34 R80 R83 R84 R86-R89 R91-R94 R96-R107 R109-R114 R116-R162 = R: signal model: DEFAULT_RESISTOR_100.000000OHM_1_2
R9 R10 = R: signal model: DEFAULT_RESISTOR_100000OHM_1_2
R77-R79 R81 = R: signal model: DEFAULT_RESISTOR_0.001OHM_1_2
R163-R168 R170-R183 R186 R190-R194 = Resistor
SW1 = PushButton_1
SW2 = SW_PB_SPST
TP1-TP8 UNK1.0V1 UNK1.2V1 UNK1.8V1 UNK2.5V1 UNK3.3V2 = T POINT A
TP9 TP10 = TEST POINT
U1 = OSC_SMD
U2 = ADM706RAR
U3 = XC7A100T
U4 = ADCMP600
U5 = N25Q128
U6 = C11204-01
U7 = LM94021
U8 U9 = USBTypeCPlug
U10 = SN65LVDS31_0
U11 = DS26LV32AT
U12 = CY7C68013_1
U13 = USBCON
U14 = 24LC00
U15 = PushButton
U16-U21 = TPS74401
Y1 = XM/SM

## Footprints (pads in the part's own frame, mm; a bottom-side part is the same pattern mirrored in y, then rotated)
2MM_HOLE
  round 8.128 hole 3.2: 1(0,0)
154744-ERNI
  rect 2.7x1.199 smd: 1(-0.635,2.41) 2(4.765,2.41) 3(-0.635,-51.94) 4(4.765,-51.94)
  round 1.801 hole 1.6: 5(2,2.21) 6(2,-51.74)
  rect 0.8x0.8 smd: A1(0,0) A2(0,-1.27) A3(0,-2.54) A4(0,-3.81) A5(0,-5.08) A6(0,-6.35) A7(0,-7.62) A8(0,-8.89) A9(0,-10.16) A10(0,-11.43) A11(0,-12.7) A12(0,-13.97) A13(0,-15.24) A14(0,-16.51) A15(0,-17.78) A16(0,-19.05) A17(0,-20.32) A18(0,-21.59) A19(0,-22.86) A20(0,-24.13) A21(0,-25.4) A22(0,-26.67) A23(0,-27.94) A24(0,-29.21) A25(0,-30.48) A26(0,-31.75) A27(0,-33.02) A28(0,-34.29) A29(0,-35.56) A30(0,-36.83) A31(0,-38.1) A32(0,-39.37) A33(0,-40.64) A34(0,-41.91) A35(0,-43.18) A36(0,-44.45) A37(0,-45.72) A38(0,-46.99) A39(0,-48.26) A40(0,-49.53) B1(-1.27,0) B2(-1.27,-1.27) B3(-1.27,-2.54) B4(-1.27,-3.81) B5(-1.27,-5.08) B6(-1.27,-6.35) B7(-1.27,-7.62) B8(-1.27,-8.89) B9(-1.27,-10.16) B10(-1.27,-11.43) B11(-1.27,-12.7) B12(-1.27,-13.97) B13(-1.27,-15.24) B14(-1.27,-16.51) B15(-1.27,-17.78) B16(-1.27,-19.05) B17(-1.27,-20.32) B18(-1.27,-21.59) B19(-1.27,-22.86) B20(-1.27,-24.13) B21(-1.27,-25.4) B22(-1.27,-26.67) B23(-1.27,-27.94) B24(-1.27,-29.21) B25(-1.27,-30.48) B26(-1.27,-31.75) B27(-1.27,-33.02) B28(-1.27,-34.29) B29(-1.27,-35.56) B30(-1.27,-36.83) B31(-1.27,-38.1) B32(-1.27,-39.37) B33(-1.27,-40.64) B34(-1.27,-41.91) B35(-1.27,-43.18) B36(-1.27,-44.45) B37(-1.27,-45.72) B38(-1.27,-46.99) B39(-1.27,-48.26) B40(-1.27,-49.53)
ARTIX7XCA100T484
  round 0.5 smd: A1(0,0) A2(1,0) A3(2,0) A4(3,0) A5(4,0) A6(5,0) A7(6,0) A8(7,0) A9(8,0) A10(9,0) A11(10,0) A12(11,0) A13(12,0) A14(13,0) A15(14,0) A16(15,0) A17(16,0) A18(17,0) A19(18,0) A20(19,0) A21(20,0) A22(21,0) AA1(0,-20) AA2(1,-20) AA3(2,-20) AA4(3,-20) AA5(4,-20) AA6(5,-20) AA7(6,-20) AA8(7,-20) AA9(8,-20) AA10(9,-20) AA11(10,-20) AA12(11,-20) AA13(12,-20) AA14(13,-20) AA15(14,-20) AA16(15,-20) AA17(16,-20) AA18(17,-20) AA19(18,-20) AA20(19,-20) AA21(20,-20) AA22(21,-20) AB1(0,-21) AB2(1,-21) AB3(2,-21) AB4(3,-21) AB5(4,-21) AB6(5,-21) AB7(6,-21) AB8(7,-21) AB9(8,-21) AB10(9,-21) AB11(10,-21) AB12(11,-21) AB13(12,-21) AB14(13,-21) AB15(14,-21) AB16(15,-21) AB17(16,-21) AB18(17,-21) AB19(18,-21) AB20(19,-21) AB21(20,-21) AB22(21,-21) B1(0,-1) B2(1,-1) B3(2,-1) B4(3,-1) B5(4,-1) B6(5,-1) B7(6,-1) B8(7,-1) B9(8,-1) B10(9,-1) B11(10,-1) B12(11,-1) B13(12,-1) B14(13,-1) B15(14,-1) B16(15,-1) B17(16,-1) B18(17,-1) B19(18,-1) B20(19,-1) B21(20,-1) B22(21,-1) C1(0,-2) C2(1,-2) C3(2,-2) C4(3,-2) C5(4,-2) C6(5,-2) C7(6,-2) C8(7,-2) C9(8,-2) C10(9,-2) C11(10,-2) C12(11,-2) C13(12,-2) C14(13,-2) C15(14,-2) C16(15,-2) C17(16,-2) C18(17,-2) C19(18,-2) C20(19,-2) C21(20,-2) C22(21,-2) D1(0,-3) D2(1,-3) D3(2,-3) D4(3,-3) D5(4,-3) D6(5,-3) D7(6,-3) D8(7,-3) D9(8,-3) D10(9,-3) D11(10,-3) D12(11,-3) D13(12,-3) D14(13,-3) D15(14,-3) D16(15,-3) D17(16,-3) D18(17,-3) D19(18,-3) D20(19,-3) D21(20,-3) D22(21,-3) E1(0,-4) E2(1,-4) E3(2,-4) E4(3,-4) E5(4,-4) E6(5,-4) E7(6,-4) E8(7,-4) E9(8,-4) E10(9,-4) E11(10,-4) E12(11,-4) E13(12,-4) E14(13,-4) E15(14,-4) E16(15,-4) E17(16,-4) E18(17,-4) E19(18,-4) E20(19,-4) E21(20,-4) E22(21,-4) F1(0,-5) F2(1,-5) F3(2,-5) F4(3,-5) F5(4,-5) F6(5,-5) F7(6,-5) F8(7,-5) F9(8,-5) F10(9,-5) F11(10,-5) F12(11,-5) F13(12,-5) F14(13,-5) F15(14,-5) F16(15,-5) F17(16,-5) F18(17,-5) F19(18,-5) F20(19,-5) F21(20,-5) F22(21,-5) G1(0,-6) G2(1,-6) G3(2,-6) G4(3,-6) G5(4,-6) G6(5,-6) G7(6,-6) G8(7,-6) G9(8,-6) G10(9,-6) G11(10,-6) G12(11,-6) G13(12,-6) G14(13,-6) G15(14,-6) G16(15,-6) G17(16,-6) G18(17,-6) G19(18,-6) G20(19,-6) G21(20,-6) G22(21,-6) H1(0,-7) H2(1,-7) H3(2,-7) H4(3,-7) H5(4,-7) H6(5,-7) H7(6,-7) H8(7,-7) H9(8,-7) H10(9,-7) H11(10,-7) H12(11,-7) H13(12,-7) H14(13,-7) H15(14,-7) H16(15,-7) H17(16,-7) H18(17,-7) H19(18,-7) H20(19,-7) H21(20,-7) H22(21,-7) J1(0,-8) J2(1,-8) J3(2,-8) J4(3,-8) J5(4,-8) J6(5,-8) J7(6,-8) J8(7,-8) J9(8,-8) J10(9,-8) J11(10,-8) J12(11,-8) J13(12,-8) J14(13,-8) J15(14,-8) J16(15,-8) J17(16,-8) J18(17,-8) J19(18,-8) J20(19,-8) J21(20,-8) J22(21,-8) K1(0,-9) K2(1,-9) K3(2,-9) K4(3,-9) K5(4,-9) K6(5,-9) K7(6,-9) K8(7,-9) K9(8,-9) K10(9,-9) K11(10,-9) K12(11,-9) K13(12,-9) K14(13,-9) K15(14,-9) K16(15,-9) K17(16,-9) K18(17,-9) K19(18,-9) K20(19,-9) K21(20,-9) K22(21,-9) L1(0,-10) L2(1,-10) L3(2,-10) L4(3,-10) L5(4,-10) L6(5,-10) L7(6,-10) L8(7,-10) L9(8,-10) L10(9,-10) L11(10,-10) L12(11,-10) L13(12,-10) L14(13,-10) L15(14,-10) L16(15,-10) L17(16,-10) L18(17,-10) L19(18,-10) L20(19,-10) L21(20,-10) L22(21,-10) M1(0,-11) M2(1,-11) M3(2,-11) M4(3,-11) M5(4,-11) M6(5,-11) M7(6,-11) M8(7,-11) M9(8,-11) M10(9,-11) M11(10,-11) M12(11,-11) M13(12,-11) M14(13,-11) M15(14,-11) M16(15,-11) M17(16,-11) M18(17,-11) M19(18,-11) M20(19,-11) M21(20,-11) M22(21,-11) N1(0,-12) N2(1,-12) N3(2,-12) N4(3,-12) N5(4,-12) N6(5,-12) N7(6,-12) N8(7,-12) N9(8,-12) N10(9,-12) N11(10,-12) N12(11,-12) N13(12,-12) N14(13,-12) N15(14,-12) N16(15,-12) N17(16,-12) N18(17,-12) N19(18,-12) N20(19,-12) N21(20,-12) N22(21,-12) P1(0,-13) P2(1,-13) P3(2,-13) P4(3,-13) P5(4,-13) P6(5,-13) P7(6,-13) P8(7,-13) P9(8,-13) P10(9,-13) P11(10,-13) P12(11,-13) P13(12,-13) P14(13,-13) P15(14,-13) P16(15,-13) P17(16,-13) P18(17,-13) P19(18,-13) P20(19,-13) P21(20,-13) P22(21,-13) R1(0,-14) R2(1,-14) R3(2,-14) R4(3,-14) R5(4,-14) R6(5,-14) R7(6,-14) R8(7,-14) R9(8,-14) R10(9,-14) R11(10,-14) R12(11,-14) R13(12,-14) R14(13,-14) R15(14,-14) R16(15,-14) R17(16,-14) R18(17,-14) R19(18,-14) R20(19,-14) R21(20,-14) R22(21,-14) T1(0,-15) T2(1,-15) T3(2,-15) T4(3,-15) T5(4,-15) T6(5,-15) T7(6,-15) T8(7,-15) T9(8,-15) T10(9,-15) T11(10,-15) T12(11,-15) T13(12,-15) T14(13,-15) T15(14,-15) T16(15,-15) T17(16,-15) T18(17,-15) T19(18,-15) T20(19,-15) T21(20,-15) T22(21,-15) U1(0,-16) U2(1,-16) U3(2,-16) U4(3,-16) U5(4,-16) U6(5,-16) U7(6,-16) U8(7,-16) U9(8,-16) U10(9,-16) U11(10,-16) U12(11,-16) U13(12,-16) U14(13,-16) U15(14,-16) U16(15,-16) U17(16,-16) U18(17,-16) U19(18,-16) U20(19,-16) U21(20,-16) U22(21,-16) V1(0,-17) V2(1,-17) V3(2,-17) V4(3,-17) V5(4,-17) V6(5,-17) V7(6,-17) V8(7,-17) V9(8,-17) V10(9,-17) V11(10,-17) V12(11,-17) V13(12,-17) V14(13,-17) V15(14,-17) V16(15,-17) V17(16,-17) V18(17,-17) V19(18,-17) V20(19,-17) V21(20,-17) V22(21,-17) W1(0,-18) W2(1,-18) W3(2,-18) W4(3,-18) W5(4,-18) W6(5,-18) W7(6,-18) W8(7,-18) W9(8,-18) W10(9,-18) W11(10,-18) W12(11,-18) W13(12,-18) W14(13,-18) W15(14,-18) W16(15,-18) W17(16,-18) W18(17,-18) W19(18,-18) W20(19,-18) W21(20,-18) W22(21,-18) Y1(0,-19) Y2(1,-19) Y3(2,-19) Y4(3,-19) Y5(4,-19) Y6(5,-19) Y7(6,-19) Y8(7,-19) Y9(8,-19) Y10(9,-19) Y11(10,-19) Y12(11,-19) Y13(12,-19) Y14(13,-19) Y15(14,-19) Y16(15,-19) Y17(16,-19) Y18(17,-19) Y19(18,-19) Y20(19,-19) Y21(20,-19) Y22(21,-19)
C11204_01
  round 0.889 hole 0.635: 1(1.45,2.8) 2(1.45,4.07) 3(1.45,5.34) 4(1.45,6.61) 5(1.45,7.88) 6(1.45,9.15) 7(1.45,10.42) 8(1.45,11.69) 9(1.45,12.96) 10(1.45,14.23) 11(17.95,14.23) 12(17.95,12.96) 13(17.95,11.69) 14(17.95,10.42) 15(17.95,9.15) 16(17.95,7.88)
CFP16ANDSOIC16
  rect 4.5x0.48 smd: 1(-0.229,9.601) 2(-0.229,8.331) 3(-0.229,7.061) 4(-0.229,5.791) 5(-0.229,4.521) 6(-0.229,3.251) 7(-0.229,1.981) 8(-0.229,0.711) 9(6.96,0.711) 10(6.96,1.981) 11(6.96,3.251) 12(6.96,4.521) 13(6.96,5.791) 14(6.96,7.061) 15(6.96,8.331) 16(6.96,9.601)
CHV
  round 1.5 hole 0.9: 1(0,0) 2(6.299,0)
CON-BNC-S-T
  round 2.54 hole 1.524: 1(0,0) 2(2.54,-2.54) 3(2.54,2.54) 4(-2.54,2.54) 5(-2.54,-2.54)
CONN_USB_B_CHL
  round 0.94 hole 0.94 unplated: (-2.2,1.445) (2.2,1.445)
  rect 0.508x2.032 smd: 1(-1.6,4.045) 2(-0.8,4.045) 3(0,4.045) 4(0.8,4.045) 5(1.6,4.045)
  rect 2.489x2.184 smd: 6(4.2,3.795) 7(4.2,-1.505) 8(-4.2,-1.505) 9(-4.2,3.795)
CT1206
  rect 1.651x1.88 smd: 1(-1.632,0) 2(1.632,0)
DIP8-100-300
  rect 1.27x1.27 hole 0.813: 1(-3.81,-3.81)
  round 1.27 hole 0.813: 2(-1.27,-3.81) 3(1.27,-3.81) 4(3.81,-3.81) 5(3.81,3.81) 6(1.27,3.81) 7(-1.27,3.81) 8(-3.81,3.81)
GND40
  round 1.524 hole 1.016: 1(0,0)
INDC2-200-M
  round 2.286 hole 1.397: 1(-2.54,0) 2(2.54,0)
JTAG-14P
  rect 1.397x1.397 hole 1.016: 1(5.131,3.226)
  round 1.397 hole 1.016: 2(5.131,5.766) 3(7.671,3.226) 4(7.671,5.766) 5(10.211,3.226) 6(10.211,5.766) 7(12.751,3.226) 8(12.751,5.766) 9(15.291,3.226) 10(15.291,5.766) 11(17.831,3.226) 12(17.831,5.766) 13(20.371,3.226) 14(20.371,5.766)
LASER22-4816-M
  round 1.016 hole 1.016 unplated: (-3.988,3.734) (-3.988,-10.516) (0.711,3.734) (0.711,-10.516) (5.69,3.734) (5.69,-10.516) (10.312,1.397) (10.312,-3.404) (10.312,-8.204)
  round 1.778 hole 1.778 unplated: (4.089,1.397) (4.089,-8.204)
  rect 2.54x0.508 smd: 1(0,0) 2(0,-0.813) 3(0,-1.6) 4(0,-2.388) 5(0,-3.2) 6(0,-3.988) 7(0,-4.801) 8(0,-5.588) 9(0,-6.401) 10(0,-7.188) 11(8.204,-6.807) 12(8.204,-5.994) 13(8.204,-5.207) 14(8.204,-4.394) 15(8.204,-3.607) 16(8.204,-2.794) 17(8.204,-2.007) 18(8.204,-1.194) 19(8.204,-0.406) 20(8.204,0.406)
  rect 2.032x2.032 hole 1.27: 23(-21.311,-10.516) 24(-11.303,-10.516) 26(-1.803,-10.516) 29(8.204,-10.516) 37(-6.807,3.734) 38(-16.307,3.734) 39(-26.289,3.734) 40(-26.391,-4.851) 41(-6.807,-7.341) 42(-6.807,-1.956)
  rect 2.032x2.032 hole 1.016: 34(3.2,3.734)
MAA05A
  rect 1.168x0.356 smd: 1(-0.978,0.65) 2(-0.978,0) 3(-0.978,-0.65) 4(0.978,-0.65) 5(0.978,0.65)
QFN65P500X500-21
  rect 1.049x0.35 smd: 1(-2.349,1.301) 2(-2.349,0.65) 3(-2.349,0) 4(-2.349,-0.65) 5(-2.349,-1.301) 11(2.349,-1.301) 12(2.349,-0.65) 13(2.349,0) 14(2.349,0.65) 15(2.349,1.301)
  rect 0.35x1.049 smd: 6(-1.301,-2.349) 7(-0.65,-2.349) 8(0,-2.349) 9(0.65,-2.349) 10(1.301,-2.349) 16(1.301,2.349) 17(0.65,2.349) 18(0,2.349) 19(-0.65,2.349) 20(-1.301,2.349)
  rect 3x3 smd: 21(0,0)
SC0402
  rect 0.635x0.508 smd: 1(-0.508,0) 2(0.508,0)
SC0603
  rect 0.813x0.889 smd: 1(-0.762,0) 2(0.762,0)
SD0805
  rect 1.016x1.27 smd: 1(-1.143,0) 2(1.143,0)
SIP-2P
  rect 1.524x1.524 hole 1.016: 1(-1.27,0)
  round 1.524 hole 1.016: 2(1.27,0)
SIP-3P
  rect 1.524x1.524 hole 1.016: 1(-2.54,0)
  round 1.524 hole 1.016: 2(0,0) 3(2.54,0)
SIP-4P-156
  rect 2.794x2.794 hole 1.778: 1(-5.944,0)
  round 2.794 hole 1.778: 2(-1.981,0) 3(1.981,0) 4(5.944,0)
SL0805
  rect 1.016x1.27 smd: 1(-0.889,0) 2(0.889,0)
SL1206
  rect 1.397x1.651 smd: 1(-1.397,0) 2(1.397,0)
SL1210
  rect 1.397x2.413 smd: 1(-1.397,0) 2(1.397,0)
SL1812
  rect 1.524x3.175 smd: 1(-2.286,0) 2(2.286,0)
SO16_50P300X413
  rect 2.032x0.635 smd: 1(-4.686,4.445) 2(-4.686,3.175) 3(-4.686,1.905) 4(-4.686,0.635) 5(-4.686,-0.635) 6(-4.686,-1.905) 7(-4.686,-3.175) 8(-4.686,-4.445) 9(4.686,-4.445) 10(4.686,-3.175) 11(4.686,-1.905) 12(4.686,-0.635) 13(4.686,0.635) 14(4.686,1.905) 15(4.686,3.175) 16(4.686,4.445)
SOP8-50-160
  rect 0.635x1.778 smd: 1(-1.905,-2.794) 2(-0.635,-2.794) 3(0.635,-2.794) 4(1.905,-2.794) 5(1.905,2.794) 6(0.635,2.794) 7(-0.635,2.794) 8(-1.905,2.794)
SOP56-25-300
  rect 0.305x1.778 smd: 1(-8.572,-4.953) 2(-7.938,-4.953) 3(-7.303,-4.953) 4(-6.668,-4.953) 5(-6.032,-4.953) 6(-5.397,-4.953) 7(-4.763,-4.953) 8(-4.128,-4.953) 9(-3.493,-4.953) 10(-2.857,-4.953) 11(-2.223,-4.953) 12(-1.587,-4.953) 13(-0.953,-4.953) 14(-0.318,-4.953) 15(0.318,-4.953) 16(0.953,-4.953) 17(1.587,-4.953) 18(2.223,-4.953) 19(2.857,-4.953) 20(3.493,-4.953) 21(4.128,-4.953) 22(4.763,-4.953) 23(5.397,-4.953) 24(6.032,-4.953) 25(6.668,-4.953) 26(7.303,-4.953) 27(7.938,-4.953) 28(8.572,-4.953) 29(8.572,4.953) 30(7.938,4.953) 31(7.303,4.953) 32(6.668,4.953) 33(6.032,4.953) 34(5.397,4.953) 35(4.763,4.953) 36(4.128,4.953) 37(3.493,4.953) 38(2.857,4.953) 39(2.223,4.953) 40(1.587,4.953) 41(0.953,4.953) 42(0.318,4.953) 43(-0.318,4.953) 44(-0.953,4.953) 45(-1.587,4.953) 46(-2.223,4.953) 47(-2.857,4.953) 48(-3.493,4.953) 49(-4.128,4.953) 50(-4.763,4.953) 51(-5.397,4.953) 52(-6.032,4.953) 53(-6.668,4.953) 54(-7.303,4.953) 55(-7.938,4.953) 56(-8.572,4.953)
SOT23-5
  rect 0.508x1.016 smd: 1(-0.94,-1.295) 2(0,-1.295) 3(0.94,-1.295) 4(0.94,1.295) 5(-0.94,1.295)
SR0603
  rect 0.813x0.889 smd: 1(-0.762,0) 2(0.762,0)
STC3528
  rect 2.032x2.286 smd: 1(-1.651,0) 2(1.651,0)
SX4-0705
  rect 1.778x2.032 smd: 1(-2.54,-2.101) 2(2.54,-2.101) 3(2.54,2.101) 4(-2.54,2.101)
TP-40-SMD
  round 1.016 smd: 1(0,0)
USB_TYPEC_PLUG_V1
  rect 1.143x2.032 hole 1.321x2.311 unplated: (-4.32,0.89) (4.32,0.89)
  rect 1.143x2.54 hole 1.321x2.794 unplated: (-4.32,-4.47) (4.32,-4.47)
  rect 0.33x0.838 smd: 1(-3,1.27) 2(-2.5,1.27) 3(-2,1.27) 4(-1.5,1.27) 5(-1,1.27) 6(-0.5,1.27) 7(0.5,1.27) 8(1,1.27) 9(1.5,1.27) 10(2,1.27) 11(2.5,1.27) 12(3,1.27) 14(2.25,0) 15(1.75,0) 16(1.25,0) 17(0.75,0) 18(0.25,0) 19(-0.25,0) 20(-0.75,0) 21(-1.25,0) 22(-1.75,0) 23(-2.25,0)
  rect 1.067x0.762 smd: 13(3.1,0) 24(-3.1,0)
XO75L
  rect 1.6x1.499 smd: 1(-2.54,-1.956) 2(0,-1.956) 3(2.54,-1.956) 4(2.54,1.956) 5(0,1.956) 6(-2.54,1.956)
XTAL2-200A
  round 1.27 hole 0.813: 1(-2.54,0) 2(2.54,0)

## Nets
1.0V: C36.1 C37.1 C38.1 C39.1 C40.1 C41.1 C42.1 C44.1 C65.1 C66.1 C67.1 C68.1 C69.1 C70.1 C71.1 C72.1 C73.1 C74.1 C75.1 C76.1 C77.1 C78.1 C85.1 C86.1 C87.1 C88.1 R184.1 R193.2 U3.D6(MGTAVCC_1) U3.D10(MGTAVCC_2) U3.E8(MGTAVCC_5) U3.F7(MGTAVCC_3) U3.F9(MGTAVCC_4) U3.H8(VCCINT#H8) U3.H10(VCCINT#H10) U3.J7(VCCINT#J7) U3.J9(VCCINT#J9) U3.J11(VCCBRAM#J11) U3.K8(VCCINT#K8) U3.L7(VCCINT#L7) U3.L11(VCCBRAM#L11) U3.M8(VCCINT#M8) U3.N7(VCCINT#N7) U3.N11(VCCBRAM#N11) U3.P8(VCCINT#P8) U3.P10(VCCINT#P10) U3.R7(VCCINT#R7) U3.R9(VCCINT#R9) U3.T8(VCCINT#T8) U3.T10(VCCINT#T10) UNK1.0V1.1
1.0V_OUT: C145.1 R171.1 R175.2 R193.1 U18.1(OUT4) U18.18(OUT1) U18.19(OUT2) U18.20(OUT3)
1.2V: C46.1 C47.1 C48.1 C49.1 R34.1 R182.2 R189.1 U3.B5(MGTAVTT_1) U3.B7(MGTAVTT_2) U3.B9(MGTAVTT_3) U3.B11(MGTAVTT_4) U3.C4(MGTAVTT_5) U3.C8(MGTAVTT_6) UNK1.2V1.1
1.2V_OUT: C137.1 R164.1 R168.2 R182.1 U17.1(OUT4) U17.18(OUT1) U17.19(OUT2) U17.20(OUT3)
1.8V: C79.1 C80.1 C81.1 C82.1 C83.1 C84.1 L2.2 R180.2 R188.1 U3.H12(VCCAUX#H12) U3.K12(VCCAUX#K12) U3.M12(VCCAUX#M12) U3.P12(VCCAUX#P12) U3.R11(VCCAUX#R11) UNK1.8V1.1
1.8V_OUT: C153.1 R180.1 R181.1 R186.2 U20.1(OUT4) U20.18(OUT1) U20.19(OUT2) U20.20(OUT3)
2.5V: C9.1 C10.1 C11.1 C12.1 C13.1 C14.1 C23.1 C24.1 C25.1 C26.1 C27.1 C28.1 R177.2 R187.1 U3.C1(VCCO_35_1) U3.F2(VCCO_35_2) U3.G19(VCCO_15_1) U3.H6(VCCO_35_3) U3.H16(VCCO_15_2) U3.J3(VCCO_35_4) U3.J13(VCCO_15_3) U3.K20(VCCO_15_4) U3.L17(VCCO_15_5) U3.M4(VCCO_35_5) U3.N1(VCCO_35_6) U3.N21(VCCO_15_6) UNK2.5V1.1
2.5V_OUT: C144.1 R170.1 R174.2 R177.1 U19.1(OUT4) U19.18(OUT1) U19.19(OUT2) U19.20(OUT3)
3.3V: C2.2 C6.1 C7.1 C8.1 C15.1 C16.1 C17.1 C18.1 C19.1 C20.1 C21.1 C22.1 C29.1 C30.1 C31.1 C32.1 C33.1 C34.1 C57.1 C58.1 C59.1 C60.1 C61.1 C89.1 C90.1 C91.1 C92.1 C93.1 C94.1 C95.1 C96.1 C97.1 C98.1 C99.1 C108.2 C109.2 C110.2 C111.2 C112.2 C113.2 C114.2 C124.1 C125.1 C131.1 C132.1 C164.2 C165.2 C166.2 C167.2 DR1.2 DR2.2 DR3.2 DR4.2 DR5.2 DR6.2 DR9.2 DR10.2 DR11.2 DR17.1 DR18.1 J7.2(VREF) L1.1 L3.1 L4.2 L5.2 O1.6(VDD) R3.2 R5.2 R9.2 R10.1 R25.2 R35.2 R36.2 R37.2 R42.1 R43.2 R44.2 R45.2 R46.2 R60.2 R61.2 R62.2 R63.2 R64.2 R65.2 R176.2 R185.1 U2.2(VCC) U3.A17(VCCO_16_1) U3.AA7(VCCO_34_1) U3.AA17(VCCO_13_1) U3.AB4(VCCO_34_2) U3.AB14(VCCO_13_2) U3.B14(VCCO_16_2) U3.C21(VCCO_16_3) U3.D18(VCCO_16_4) U3.E15(VCCO_16_5) U3.F12(VCCO_0_1) U3.F22(VCCO_16_6) U3.M14(VCCO_14_1) U3.P18(VCCO_14_2) U3.R5(VCCO_34_3) U3.R15(VCCO_14_3) U3.T2(VCCO_34_4) U3.T12(VCCO_0_2) U3.T22(VCCO_14_4) U3.U8(CFGBVS_0) U3.U11(M0_0) U3.U19(VCCO_14_5) U3.V6(VCCO_34_5) U3.V16(VCCO_13_3) U3.W3(VCCO_34_6) U3.W13(VCCO_13_4) U3.Y10(VCCO_13_5) U3.Y20(VCCO_14_6) U4.5(VCCI/VCCO) U5.2(VCC) U10.4(G) U10.16(VCC) U11.4(EN) U11.16(VCC) U12.6(VCC#6) U12.18(VCC#18) U12.24(VCC#24) U12.34(VCC#34) U12.39(VCC#39) U12.50(VCC#50) U14.8(VCC) UNK3.3V2.1
3.3V_OUT: C136.1 R163.1 R167.2 R176.1 U16.1(OUT4) U16.18(OUT1) U16.19(OUT2) U16.20(OUT3)
3.3V_OUT_DET: C159.1 R157.1 R159.2 R161.1 R162.2 R190.1 R192.2 U21.1(OUT4) U21.18(OUT1) U21.19(OUT2) U21.20(OUT3)
5.0V_HV: C101.2 C154.1 C155.1 C158.1 C160.1 L7.2 R51.1 R136.2 R140.2 TP9.1 U6.1(VCC) U21.5(IN1) U21.6(IN2) U21.7(IN3) U21.8(IN4) U21.10(BIAS) U21.11(EN)
+5VIN: J18.2 L6.1 L7.1 R179.2 R194.1
AVCC: C116.2 C117.2 C118.2 C119.2 L3.2 U12.10(AVCC) U12.14(AVCC#14)
VCC5V0: C134.1 C135.1 C138.1 C139.1 C142.1 C143.1 C146.1 C147.1 C150.1 C151.1 C152.1 C156.1 L6.2 U16.5(IN1) U16.6(IN2) U16.7(IN3) U16.8(IN4) U16.10(BIAS) U16.11(EN) U17.5(IN1) U17.6(IN2) U17.7(IN3) U17.8(IN4) U17.10(BIAS) U17.11(EN) U18.5(IN1) U18.6(IN2) U18.7(IN3) U18.8(IN4) U18.10(BIAS) U18.11(EN) U19.5(IN1) U19.6(IN2) U19.7(IN3) U19.8(IN4) U19.10(BIAS) U19.11(EN) U20.5(IN1) U20.6(IN2) U20.7(IN3) U20.8(IN4) U20.10(BIAS) U20.11(EN)
VCCADC: C63.1 C64.1 L2.1 U3.K10(VCCADC_0)
0: C2.1 C3.1 C4.1 C6.2 C7.2 C8.2 C9.2 C10.2 C11.2 C12.2 C13.2 C14.2 C15.2 C16.2 C17.2 C18.2 C19.2 C20.2 C21.2 C22.2 C23.2 C24.2 C25.2 C26.2 C27.2 C28.2 C29.2 C30.2 C31.2 C32.2 C33.2 C34.2 C36.2 C37.2 C38.2 C39.2 C40.2 C41.2 C42.2 C44.2 C46.2 C47.2 C48.2 C49.2 C57.2 C58.2 C59.2 C60.2 C61.2 C63.2 C64.2 C65.2 C66.2 C67.2 C68.2 C69.2 C70.2 C71.2 C72.2 C73.2 C74.2 C75.2 C76.2 C77.2 C78.2 C79.2 C80.2 C81.2 C82.2 C83.2 C84.2 C85.2 C86.2 C87.2 C88.2 C89.2 C90.2 C91.2 C92.2 C93.2 C94.2 C95.2 C96.2 C97.2 C98.2 C99.2 C101.1 C102.2 C103.2 C104.2 C105.2 C106.1 C107.1 C108.1 C109.1 C110.1 C111.1 C112.1 C113.1 C114.1 C115.2 C116.1 C117.1 C118.1 C119.1 C121.2 C122.2 C123.2 C124.2 C125.2 C128.2 C129.2 C130.2 C131.2 C132.2 C134.2 C135.2 C136.2 C137.2 C138.2 C139.2 C140.2 C141.2 C142.2 C143.2 C144.2 C145.2 C146.2 C147.2 C148.2 C149.2 C150.2 C151.2 C152.2 C153.2 C154.2 C155.2 C156.2 C157.2 C158.2 C159.2 C160.2 C161.2 C164.1 C165.1 C166.1 C167.1 D1.1(CATHODE) D2.1(CATHODE) D3.1(CATHODE) D4.1(CATHODE) D5.1(CATHODE) D6.1(CATHODE) D7.1(CATHODE) D8.1(CATHODE) D11.2(CATHODE) D16.2(CATHODE) D17.1(CATHODE) D18.1(CATHODE) D19.1(CATHODE) D20.1(CATHODE) D21.1(CATHODE) DR7.2 DR8.2 DR13.2 DR15.2 DR16.2 DU1.1(VEET_1) DU1.10(VEER_1) DU1.11(VEER_2) DU1.14(VEER_3) DU1.17(VEET_2) DU1.20(VEET_3) DU1.23(GND3) DU1.24(GND4) DU1.26(GND6) DU1.29(GND9) DU1.34(GND14) DU1.37(GND17) DU1.38(GND18) DU1.39(GND19) DU1.40(GND20) DU1.41(GND21) DU1.42(GND22) J1.2 J1.3 J1.4 J1.5 J2.2 J2.3 J2.4 J2.5 J3.2 J3.3 J3.4 J3.5 J4.2 J4.3 J4.4 J4.5 J5.2 J5.3 J5.4 J5.5 J6.2 J6.3 J6.4 J6.5 J7.1(G1) J7.3(G2) J7.5(G3) J7.7(G4) J7.9(G5) J7.11(G6) J7.13(G7) J8.1 J9.1(GND) J10.1(GND) J11.1(GND) J12.1(GND) J15.1 J16.1(GND#1) J16.2(GND#2) J16.3(GND#3) J16.4(GND#4) J16.5(GND#5) J16.6(GND#6) J16.A2 J16.A4 J16.A6 J16.A8 J16.A10 J16.A12 J16.A14 J16.A16 J16.A18 J16.A20 J16.A22 J16.A24 J16.A26 J16.A28 J16.A30 J16.A32 J16.A34 J16.A36 J16.A38 J16.A40 J16.B1 J16.B3 J16.B5 J16.B7 J16.B9 J16.B11 J16.B13 J16.B15 J16.B17 J16.B19 J16.B21 J16.B23 J16.B25 J16.B27 J16.B29 J16.B31 J16.B33 J16.B35 J16.B37 J16.B39 J17.1(GND#1) J17.2(GND#2) J17.3(GND#3) J17.4(GND#4) J17.5(GND#5) J17.6(GND#6) J17.A1 J17.A2 J17.A5 J17.A6 J17.A9 J17.A10 J17.A12 J17.A14 J17.A16 J17.A18 J17.A20 J17.A22 J17.A25 J17.A28 J17.A30 J17.A32 J17.A34 J17.A36 J17.A38 J17.A40 J17.B3 J17.B4 J17.B7 J17.B8 J17.B11 J17.B13 J17.B15 J17.B17 J17.B19 J17.B21 J17.B23 J17.B24 J17.B27 J17.B28 J17.B29 J17.B31 J17.B33 J17.B35 J17.B37 J17.B39 J18.4 O1.3(GND) R6.1 R7.2 R20.2 R23.2 R24.2 R27.2 R29.2 R31.2 R33.2 R47.1 R53.1 R165.2 R166.2 R172.2 R173.2 R178.2 R183.2 R191.2 SW2.1 U1.2(GND) U2.3(GND) U3.A2(GND#A2) U3.A3(GND#A3) U3.A5(GND#A5) U3.A7(GND#A7) U3.A9(GND#A9) U3.A11(GND#A11) U3.A12(GND#A12) U3.A22(GND#A22) U3.AA2(GND#AA2) U3.AA12(GND#AA12) U3.AA22(GND#AA22) U3.AB9(GND#AB9) U3.AB19(GND#AB19) U3.B3(GND#B3) U3.B12(GND#B12) U3.B19(GND#B19) U3.C3(GND#C3) U3.C6(GND#C6) U3.C10(GND#C10) U3.C12(GND#C12) U3.C16(GND#C16) U3.D3(GND#D3) U3.D4(GND#D4) U3.D8(GND#D8) U3.D12(GND#D12) U3.D13(GND#D13) U3.E4(GND#E4) U3.E5(GND#E5) U3.E7(GND#E7) U3.E9(GND#E9) U3.E11(GND#E11) U3.E12(VCCBATT_0) U3.E20(GND#E20) U3.F5(GND#F5) U3.F11(GND#F11) U3.F17(GND#F17) U3.G5(GND#G5) U3.G6(GND#G6) U3.G7(GND#G7) U3.G8(GND#G8) U3.G9(GND#G9) U3.G10(GND#G10) U3.G12(GND#G12) U3.G14(GND#G14) U3.H1(GND#H1) U3.H7(GND#H7) U3.H9(GND#H9) U3.H11(GND#H11) U3.H21(GND#H21) U3.J8(GND#J8) U3.J10(GND#J10) U3.J12(GND#J12) U3.J18(GND#J18) U3.K5(GND#K5) U3.K7(GND#K7) U3.K9(GNDADC_0) U3.K11(GND#K11) U3.K15(GND#K15) U3.L2(GND#L2) U3.L8(GND#L8) U3.L9(VREFN_0) U3.L10(VP_0) U3.L22(GND#L22) U3.M7(GND#M7) U3.M9(VN_0) U3.M10(VREFP_0) U3.M11(GND#M11) U3.M19(GND#M19) U3.N6(GND#N6) U3.N8(GND#N8) U3.N9(DXN_0) U3.N10(DXP_0) U3.N16(GND#N16) U3.P3(GND#P3) U3.P7(GND#P7) U3.P9(GND#P9) U3.P11(GND#P11) U3.P13(GND#P13) U3.R8(GND#R8) U3.R10(GND#R10) U3.R12(GND#R12) U3.R20(GND#R20) U3.T7(GND#T7) U3.T9(GND#T9) U3.T11(GND#T11) U3.T17(GND#T17) U3.U4(GND#U4) U3.U10(M1_0) U3.U14(GND#U14) U3.U22(IO_L3P_T0_DQS_PUDC_B_14) U3.V1(GND#V1) U3.V11(GND#V11) U3.V21(GND#V21) U3.W8(GND#W8) U3.W18(GND#W18) U3.Y5(GND#Y5) U3.Y15(GND#Y15) U4.2(VEE) U5.10(VSS) U6.2(GND#2) U6.5(GND#5) U6.8(GND#8) U6.15(GND#15) U7.1(GS0) U7.2(GND) U7.5(GS1) U8.1(A1 GND) U8.12(A12 GND) U8.13(B1 GND) U8.24(B12 GND) U9.1(A1 GND) U9.12(A12 GND) U9.13(B1 GND) U9.24(B12 GND) U10.8(GND) U10.12(/G) U11.8(GND) U11.12(EN*) U12.4(GND#4) U12.7(GND#7) U12.13(AGND) U12.17(AGND#17) U12.19(GND#19) U12.33(GND#33) U12.35(GND#35) U12.48(GND#48) U13.5(GND) U13.6 U13.7 U13.8 U13.9 U14.2(A1) U14.3(A2) U14.4(VSS) U14.7(WP) U15.1 U16.12(GND) U16.21(PAD) U17.12(GND) U17.21(PAD) U18.12(GND) U18.21(PAD) U19.12(GND) U19.21(PAD) U20.12(GND) U20.21(PAD) U21.12(GND) U21.21(PAD)
/BUTTON_LOW: R7.1 SW1.1
CCLK: U3.L12(CCLK_0) U5.16(C)
DONE: D9.2(ANODE) R44.1 U3.G11(DONE_0)
FIFOADR0: U3.V18(IO_L14P_T2_SRCC_14) U12.44(PA4/FIFOADR0)
FIFOADR1: U3.AA21(IO_L8N_T1_D12_14) U12.45(PA5/FIFOADR1)
FLASH_CS_B: R37.1 U3.T19(IO_L6P_T0_FCS_B_14) U5.7(\\S)
FLASH_DQ0: U3.P22(IO_L1P_T0_D00_MOSI_14) U5.15(DQ0)
FLASH_DQ1: U3.R22(IO_L1N_T0_D01_DIN_14) U5.8(DQ1)
FLASH_DQ2: R36.1 U3.P21(IO_L2P_T0_D02_14) U5.9(\\W/VPP/DQ2)
FLASH_DQ3: R35.1 U3.R21(IO_L2N_T0_D03_14) U5.1(\\H\O\L\D/DQ3)
FPGA_LED1: R11.1 TP1.1(TP) U3.A20(IO_L16N_T2_16)
FPGA_LED2: R12.1 TP2.1(TP) U3.C22(IO_L20P_T3_16)
FPGA_LED3: R13.1 TP3.1(TP) U3.D21(IO_L23N_T3_16)
FPGA_LED4: R14.1 TP4.1(TP) U3.E21(IO_L23P_T3_16)
FPGA_LED5: R15.1 TP5.1(TP) U3.E22(IO_L22P_T3_16)
FPGA_LED6: R16.1 TP6.1(TP) U3.F20(IO_L18N_T2_16)
FPGA_LED7: R17.1 TP7.1(TP) U3.G21(IO_L24P_T3_16)
FPGA_LED8: R18.1 TP8.1(TP) U3.G22(IO_L24N_T3_16)
GTP0_RD+: C126.1 DU1.13(RD_P)
GTP0_RD-: C120.1 DU1.12(RD_N)
GTP0_TD+: C127.2 DU1.18(TD_P) R67.2
GTP0_TD-: C133.2 DU1.19(TD_N) R67.1
GTP0_TX_DETECT: D13.1(CATHODE) DR3.1 DU1.6(MOD_ABS)
IN_DATA_1+: U8.6(D_P A) U8.18(D_P B) U11.2(R1+)
IN_DATA_1-: U8.7(D_N A) U8.19(D_N B) U11.1(R1-)
IN_DATA_5+: U9.2(TX1_P) U9.14(TX2_P) U11.6(R2+)
IN_DATA_5-: U9.3(TX1_N) U9.15(TX2_N) U11.7(R2-)
IN_DATA_6+: U9.11(RX2_P) U9.23(RX1_P) U11.10(R3+)
IN_DATA_6-: U9.10(RX2_N) U9.22(RX1_N) U11.9(R3-)
IN_MONITOR: R121.1 U3.K2(IO_L9P_T1_DQS_AD7P_35)
IN_TX_HV: U3.AB5(IO_L10N_T1_34) U6.4(TXD)
INIT_B: D10.1(CATHODE) R45.1 U3.U12(INIT_B_0)
IO_PRE_2.5_1: R137.1 U3.A1(IO_L1N_T0_AD4N_35)
IO_PRE_2.5_2: R139.1 U3.B1(IO_L1P_T0_AD4P_35)
IO_PRE_2.5_3: R133.2 U3.C2(IO_L2P_T0_AD12P_35)
IO_PRE_2.5_4: R135.2 U3.B2(IO_L2N_T0_AD12N_35)
IO_PRE_2.5_5: R129.1 U3.E1(IO_L3P_T0_DQS_AD5P_35)
IO_PRE_2.5_6: R131.1 U3.D1(IO_L3N_T0_DQS_AD5N_35)
IO_PRE_2.5_7: R143.2 U3.G3(IO_L11N_T1_SRCC_35)
IO_PRE_2.5_8: R149.1 U3.F4(IO_0_35)
IO_PRE_2.5_9: R151.2 U3.E2(IO_L4P_T0_35)
IO_PRE_2.5_10: R153.1 U3.E3(IO_L6N_T0_VREF_35)
IO_PRE_2.5_11: R155.2 U3.D2(IO_L4N_T0_35)
